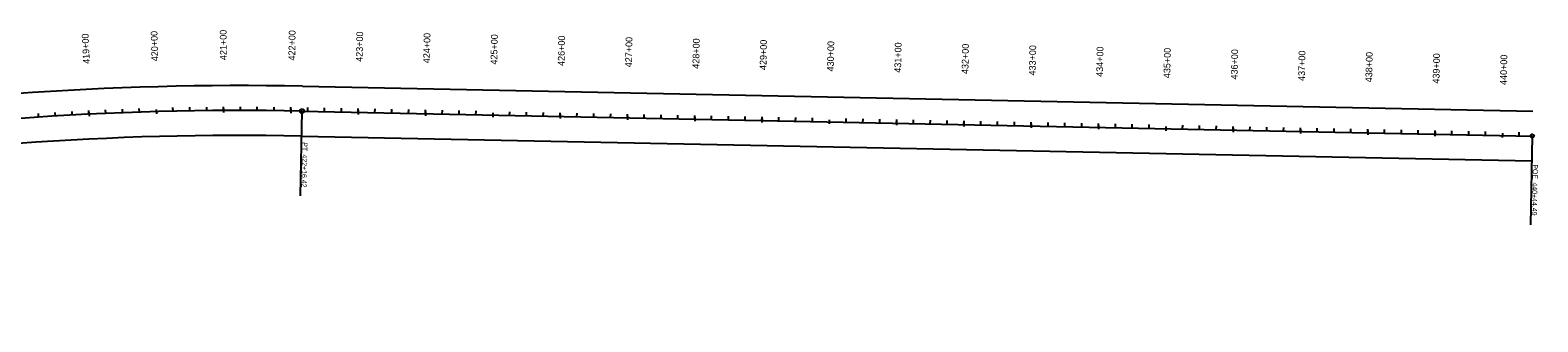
# Model space of a CAD drawing. Extents: x 21369364 to 21378321, y 8396964 to 8399934.
# Drawn here: x 21376081 to 21378321, y 8398308 to 8398741 of the extents above; entities that cross this region are included whole.
import ezdxf

# ---------------------------------------------------------------- set-up
doc = ezdxf.new("R2010")
doc.units = 0
for name, color, linetype in [('Alignment', 7, 'Continuous'), ('Level 1', 7, 'Continuous'), ('Level 60', 7, 'Continuous'), ('TextNonPlot', 7, 'Continuous')]:
    doc.layers.add(name, color=color, linetype=linetype)

msp = doc.modelspace()

# ---------------------------------------------------------------- linework, layer by layer
at = {"layer": 'Alignment'}
msp.add_line((21376485.1, 8398621), (21378312.8, 8398584), dxfattribs=at)
msp.add_arc((21376392.9, 8394061.3), 4560.6, 88.8415, 110.16, dxfattribs=at)
at = {"layer": 'Level 1'}
for p, q in [((21376485.1, 8398621), (21376482.5, 8398495)), ((21378312.8, 8398584), (21378310.1, 8398452)), ((21376482.5, 8398495), (21376482.5, 8398495)), ((21378310.1, 8398452), (21378310.1, 8398452))]:
    msp.add_line(p, q, dxfattribs=at)
for centre, radius in [((21376485.1, 8398621), 3.12), ((21378312.8, 8398584), 2.67)]:
    msp.add_circle(centre, radius, dxfattribs=at)
at = {"layer": 'Level 60'}
for p, q in [((21376093.9, 8398612.1), (21376093.5, 8398617.5)), ((21376118.8, 8398613.7), (21376118.5, 8398619.1)), ((21376143.8, 8398615.1), (21376143.5, 8398620.5)), ((21376168.6, 8398619.4), (21376168.9, 8398613.3)), ((21376193.7, 8398617.5), (21376193.5, 8398623)), ((21376218.7, 8398618.6), (21376218.5, 8398624)), ((21376243.7, 8398619.5), (21376243.5, 8398624.9)), ((21376268.6, 8398623.3), (21376268.8, 8398617.1)), ((21376293.7, 8398620.8), (21376293.5, 8398626.3)), ((21376318.7, 8398621.3), (21376318.6, 8398626.7)), ((21376343.7, 8398621.6), (21376343.6, 8398627.1)), ((21376368.6, 8398624.9), (21376368.7, 8398618.8)), ((21376393.7, 8398621.9), (21376393.7, 8398627.4)), ((21376418.7, 8398621.8), (21376418.7, 8398627.3)), ((21376443.7, 8398621.6), (21376443.7, 8398627.1)), ((21376468.7, 8398624.3), (21376468.6, 8398618.2)), ((21376493.6, 8398620.8), (21376493.8, 8398626.2)), ((21376518.6, 8398620.3), (21376518.7, 8398625.7)), ((21376543.6, 8398619.8), (21376543.7, 8398625.2)), ((21376568.7, 8398622.3), (21376568.6, 8398616.2)), ((21376593.6, 8398618.8), (21376593.7, 8398624.2)), ((21376618.6, 8398618.3), (21376618.7, 8398623.7)), ((21376643.6, 8398617.8), (21376643.7, 8398623.2)), ((21376668.7, 8398620.3), (21376668.5, 8398614.2)), ((21376693.6, 8398616.7), (21376693.7, 8398622.2)), ((21376718.6, 8398616.2), (21376718.7, 8398621.7)), ((21376743.6, 8398615.7), (21376743.7, 8398621.2)), ((21376768.6, 8398618.3), (21376768.5, 8398612.2)), ((21376793.6, 8398614.7), (21376793.7, 8398620.2)), ((21376818.6, 8398614.2), (21376818.7, 8398619.7)), ((21376843.6, 8398613.7), (21376843.7, 8398619.2)), ((21376868.6, 8398616.3), (21376868.5, 8398610.1)), ((21376893.6, 8398612.7), (21376893.7, 8398618.2)), ((21376918.6, 8398612.2), (21376918.7, 8398617.7)), ((21376943.6, 8398611.7), (21376943.7, 8398617.1)), ((21376993.5, 8398610.7), (21376993.7, 8398616.1)), ((21376968.6, 8398614.2), (21376968.5, 8398608.1)), ((21377018.5, 8398610.2), (21377018.6, 8398615.6)), ((21377043.5, 8398609.7), (21377043.6, 8398615.1)), ((21377068.6, 8398612.2), (21377068.5, 8398606.1)), ((21377093.5, 8398608.7), (21377093.6, 8398614.1)), ((21377118.5, 8398608.2), (21377118.6, 8398613.6)), ((21377143.5, 8398607.6), (21377143.6, 8398613.1)), ((21377168.6, 8398610.2), (21377168.4, 8398604.1)), ((21377193.5, 8398606.6), (21377193.6, 8398612.1)), ((21377218.5, 8398606.1), (21377218.6, 8398611.6)), ((21377243.5, 8398605.6), (21377243.6, 8398611.1)), ((21377268.5, 8398608.2), (21377268.4, 8398602.1)), ((21377293.5, 8398604.6), (21377293.6, 8398610.1)), ((21377318.5, 8398604.1), (21377318.6, 8398609.6)), ((21377343.5, 8398603.6), (21377343.6, 8398609.1)), ((21377368.5, 8398606.2), (21377368.4, 8398600)), ((21377393.5, 8398602.6), (21377393.6, 8398608)), ((21377418.5, 8398602.1), (21377418.6, 8398607.5)), ((21377443.4, 8398601.6), (21377443.6, 8398607)), ((21377468.5, 8398604.1), (21377468.4, 8398598)), ((21377493.4, 8398600.6), (21377493.5, 8398606)), ((21377518.4, 8398600.1), (21377518.5, 8398605.5)), ((21377543.4, 8398599.6), (21377543.5, 8398605)), ((21377568.5, 8398602.1), (21377568.4, 8398596)), ((21377593.4, 8398598.5), (21377593.5, 8398604)), ((21377618.4, 8398598), (21377618.5, 8398603.5)), ((21377643.4, 8398597.5), (21377643.5, 8398603)), ((21377668.5, 8398600.1), (21377668.3, 8398594)), ((21377693.4, 8398596.5), (21377693.5, 8398602)), ((21377718.4, 8398596), (21377718.5, 8398601.5)), ((21377743.4, 8398595.5), (21377743.5, 8398601)), ((21377768.4, 8398598.1), (21377768.3, 8398591.9)), ((21377793.4, 8398594.5), (21377793.5, 8398600)), ((21377818.4, 8398594), (21377818.5, 8398599.5)), ((21377843.4, 8398593.5), (21377843.5, 8398599)), ((21377868.4, 8398596), (21377868.3, 8398589.9)), ((21377893.4, 8398592.5), (21377893.5, 8398597.9)), ((21377918.4, 8398592), (21377918.5, 8398597.4)), ((21377943.3, 8398591.5), (21377943.5, 8398596.9)), ((21377968.4, 8398594), (21377968.3, 8398587.9)), ((21377993.3, 8398590.5), (21377993.4, 8398595.9)), ((21378018.3, 8398590), (21378018.4, 8398595.4)), ((21378043.3, 8398589.4), (21378043.4, 8398594.9)), ((21378093.3, 8398588.4), (21378093.4, 8398593.9)), ((21378068.4, 8398592), (21378068.3, 8398585.9)), ((21378118.3, 8398587.9), (21378118.4, 8398593.4)), ((21378143.3, 8398587.4), (21378143.4, 8398592.9)), ((21378168.4, 8398590), (21378168.2, 8398583.9)), ((21378193.3, 8398586.4), (21378193.4, 8398591.9)), ((21378218.3, 8398585.9), (21378218.4, 8398591.4)), ((21378243.3, 8398585.4), (21378243.4, 8398590.9)), ((21378268.3, 8398588), (21378268.2, 8398581.8)), ((21378293.3, 8398584.4), (21378293.4, 8398589.9))]:
    msp.add_line(p, q, dxfattribs=at)
at = {"layer": 'TextNonPlot'}
for p, q in [((21376485.8, 8398658), (21378313.5, 8398621)), ((21376168.7, 8398616.4), (21376168.5, 8398621.8)), ((21376268.6, 8398623.3), (21376268.8, 8398617.1)), ((21376368.7, 8398621.8), (21376368.6, 8398627.3)), ((21376468.6, 8398621.3), (21376468.7, 8398626.7)), ((21376568.6, 8398619.3), (21376568.7, 8398624.7)), ((21376668.6, 8398617.2), (21376668.7, 8398622.7)), ((21376768.6, 8398618.3), (21376768.5, 8398612.2)), ((21376868.6, 8398613.2), (21376868.7, 8398618.7)), ((21376968.5, 8398611.2), (21376968.7, 8398616.6)), ((21377068.5, 8398609.2), (21377068.6, 8398614.6)), ((21377168.5, 8398607.1), (21377168.6, 8398612.6)), ((21377268.5, 8398608.2), (21377268.4, 8398602.1)), ((21377368.5, 8398603.1), (21377368.6, 8398608.6)), ((21377468.4, 8398601.1), (21377468.6, 8398606.5)), ((21377568.4, 8398599.1), (21377568.5, 8398604.5)), ((21377668.4, 8398597), (21377668.5, 8398602.5)), ((21377768.4, 8398598.1), (21377768.3, 8398591.9)), ((21377868.4, 8398593), (21377868.5, 8398598.4)), ((21377968.3, 8398591), (21377968.5, 8398596.4)), ((21378068.3, 8398588.9), (21378068.4, 8398594.4)), ((21376484.3, 8398584), (21378312, 8398547)), ((21378168.3, 8398586.9), (21378168.4, 8398592.4)), ((21378268.3, 8398588), (21378268.2, 8398581.8))]:
    msp.add_line(p, q, dxfattribs=at)
for radius in [4597.6, 4523.6]:
    msp.add_arc((21376392.9, 8394061.3), radius, 88.8415, 110.16, dxfattribs=at)

# ---------------------------------------------------------------- texts
at = {"layer": 'Level 1'}
for s, p in [('PT', (21376485.8, 8398574.8)), ('422+16.42', (21376485.4, 8398556.7)), ('POE ', (21378313.6, 8398542)), ('440+44.49', (21378313, 8398515.1))]:
    msp.add_text(s, height=7.5, rotation=268.8415, dxfattribs=at).set_placement(p)
at = {"layer": 'Level 60'}
for s, rotation, p in [('419+00', 92.8168, (21376170.1, 8398691.5)), ('420+00', 91.5605, (21376271.6, 8398695.3)), ('421+00', 90.3042, (21376373.3, 8398696.9)), ('422+00', 89.0478, (21376474.9, 8398696.2)), ('423+00', 88.8415, (21376575.2, 8398694.2)), ('424+00', 88.8415, (21376675.1, 8398692.1)), ('425+00', 88.8415, (21376775.1, 8398690.1)), ('426+00', 88.8415, (21376875.1, 8398688.1)), ('427+00', 88.8415, (21376975.1, 8398686.1)), ('428+00', 88.8415, (21377075.1, 8398684)), ('429+00', 88.8415, (21377175, 8398682)), ('430+00', 88.8415, (21377275, 8398680)), ('431+00', 88.8415, (21377375, 8398678)), ('432+00', 88.8415, (21377475, 8398676)), ('433+00', 88.8415, (21377574.9, 8398673.9)), ('434+00', 88.8415, (21377674.9, 8398671.9)), ('435+00', 88.8415, (21377774.9, 8398669.9)), ('436+00', 88.8415, (21377874.9, 8398667.9)), ('437+00', 88.8415, (21377974.9, 8398665.8)), ('438+00', 88.8415, (21378074.8, 8398663.8)), ('439+00', 88.8415, (21378174.8, 8398661.8)), ('440+00', 88.8415, (21378274.8, 8398659.8))]:
    msp.add_text(s, height=10.02, rotation=rotation, dxfattribs=at).set_placement(p)
at = {"layer": 'TextNonPlot'}
for s, rotation, p in [('420+00', 91.5605, (21376271.6, 8398695.3)), ('425+00', 88.8415, (21376775.1, 8398690.1)), ('430+00', 88.8415, (21377275, 8398680)), ('435+00', 88.8415, (21377774.9, 8398669.9)), ('440+00', 88.8415, (21378274.8, 8398659.8))]:
    msp.add_text(s, height=10.02, rotation=rotation, dxfattribs=at).set_placement(p)

doc.saveas('drawing.dxf')
